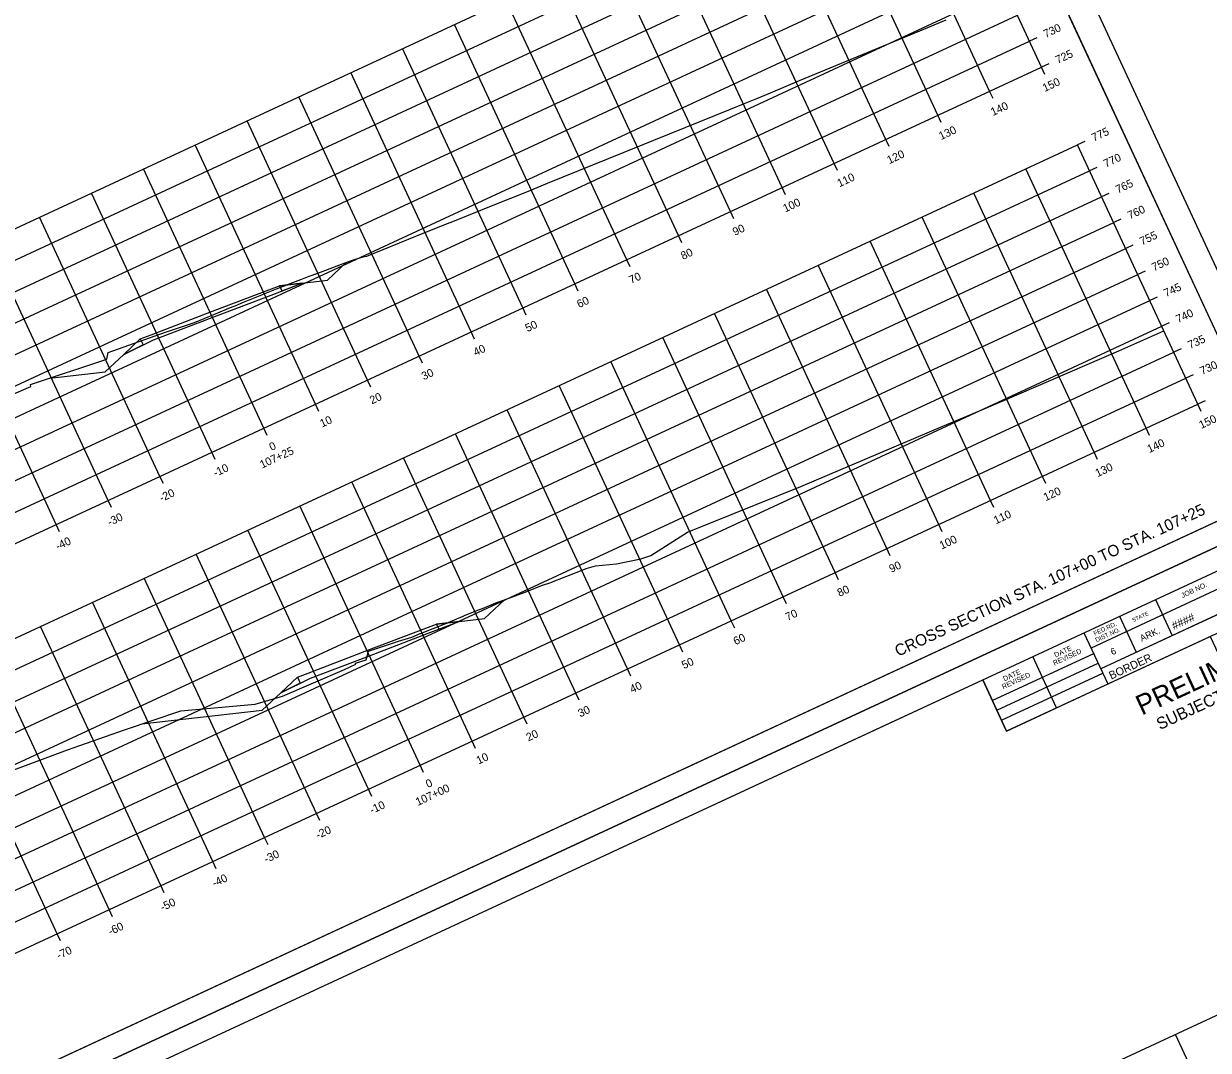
# Model space of a CAD drawing. Extents: x 1354696 to 1366163, y 660729 to 670380.
# Drawn here: x 1355130.4 to 1355337.6, y 664529.6 to 664709.1 of the extents above; entities that cross this region are included whole.
import ezdxf

# ---------------------------------------------------------------- set-up
doc = ezdxf.new("R2010")
doc.units = 0
for name, color, linetype in [('Default', 7, 'Continuous'), ('R_Alt Surface', 7, 'Continuous'), ('R_Axis', 7, 'Continuous'), ('R_Axis Annot', 7, 'Continuous'), ('R_Border', 7, 'Continuous'), ('R_Border Prem', 7, 'Continuous'), ('R_Draft', 7, 'Continuous'), ('R_Exist Surface', 7, 'Continuous'), ('R_Fin Surface', 7, 'Continuous'), ('R_Grid', 7, 'Continuous'), ('R_No Plot', 7, 'Continuous')]:
    doc.layers.add(name, color=color, linetype=linetype)

msp = doc.modelspace()

# ---------------------------------------------------------------- linework, layer by layer
at = {"layer": 'Default'}
for points in [[(1355175.1, 664663.32), (1355175.53, 664662.41), (1355179.08, 664663.77)], [(1355150.76, 664654.02), (1355151.25, 664652.95), (1355147.87, 664651.29)], [(1355202.58, 664604.14), (1355203, 664603.23), (1355206.56, 664604.59)], [(1355178.23, 664594.84), (1355178.73, 664593.77), (1355175.34, 664592.12)]]:
    msp.add_lwpolyline(points, close=True, dxfattribs=at)
at = {"layer": 'R_Alt Surface'}
for points in [[(1355147.87, 664651.29), (1355153.05, 664653.83), (1355163.35, 664657.76), (1355173.65, 664661.69), (1355179.08, 664663.77)], [(1355175.34, 664592.12), (1355180.52, 664594.65), (1355190.83, 664598.58), (1355201.13, 664602.52), (1355206.56, 664604.59)]]:
    msp.add_lwpolyline(points, dxfattribs=at)
at = {"layer": 'R_Axis'}
for p, q in [((1355308.4, 664701.56), (1355287.34, 664746.91)), ((1355307.56, 664706.68), (1355306.29, 664706.09)), ((1355036.29, 664575.23), (1355308.4, 664701.56)), ((1355309.67, 664702.15), (1355308.4, 664701.56)), ((1355308.99, 664700.29), (1355308.4, 664701.56)), ((1355299.92, 664696.08), (1355299.33, 664697.35)), ((1355290.85, 664691.86), (1355290.26, 664693.13)), ((1355281.78, 664687.65), (1355281.19, 664688.92)), ((1355315.98, 664688.54), (1355314.71, 664687.95)), ((1355335.77, 664642.6), (1355314.71, 664687.95)), ((1355272.71, 664683.44), (1355272.12, 664684.71)), ((1355318.09, 664684.01), (1355316.82, 664683.42)), ((1355263.64, 664679.23), (1355263.05, 664680.5)), ((1355320.19, 664679.47), (1355318.92, 664678.88)), ((1355254.57, 664675.02), (1355253.98, 664676.29)), ((1355322.3, 664674.94), (1355321.03, 664674.35)), ((1355245.49, 664670.81), (1355244.91, 664672.08)), ((1355324.4, 664670.4), (1355323.13, 664669.81)), ((1355236.42, 664666.6), (1355235.84, 664667.87)), ((1355326.51, 664665.87), (1355325.24, 664665.28)), ((1355227.35, 664662.39), (1355226.77, 664663.66)), ((1355328.62, 664661.33), (1355327.35, 664660.74)), ((1355218.28, 664658.18), (1355217.69, 664659.45)), ((1355330.72, 664656.8), (1355329.45, 664656.21)), ((1355209.21, 664653.97), (1355208.62, 664655.24)), ((1355332.83, 664652.26), (1355331.56, 664651.67)), ((1355200.14, 664649.75), (1355199.55, 664651.02)), ((1355334.93, 664647.73), (1355333.66, 664647.14)), ((1355191.07, 664645.54), (1355190.48, 664646.81)), ((1355063.66, 664516.27), (1355335.77, 664642.6)), ((1355182, 664641.33), (1355181.41, 664642.6)), ((1355337.04, 664643.19), (1355335.77, 664642.6)), ((1355336.36, 664641.33), (1355335.77, 664642.6)), ((1355172.93, 664637.12), (1355172.34, 664638.39)), ((1355327.29, 664637.12), (1355326.7, 664638.39)), ((1355163.86, 664632.91), (1355163.27, 664634.18)), ((1355318.22, 664632.91), (1355317.63, 664634.18)), ((1355154.79, 664628.7), (1355154.2, 664629.97)), ((1355309.15, 664628.7), (1355308.56, 664629.97)), ((1355145.72, 664624.49), (1355145.13, 664625.76)), ((1355300.08, 664624.49), (1355299.49, 664625.76)), ((1355136.65, 664620.28), (1355136.06, 664621.55)), ((1355291.01, 664620.28), (1355290.42, 664621.55)), ((1355281.94, 664616.06), (1355281.35, 664617.33)), ((1355272.87, 664611.85), (1355272.28, 664613.12)), ((1355263.8, 664607.64), (1355263.21, 664608.91)), ((1355254.73, 664603.43), (1355254.14, 664604.7)), ((1355245.66, 664599.22), (1355245.07, 664600.49)), ((1355236.59, 664595.01), (1355236, 664596.28)), ((1355227.52, 664590.8), (1355226.93, 664592.07)), ((1355218.45, 664586.59), (1355217.86, 664587.86)), ((1355209.38, 664582.38), (1355208.79, 664583.65)), ((1355200.31, 664578.17), (1355199.72, 664579.44)), ((1355191.24, 664573.95), (1355190.65, 664575.22)), ((1355182.17, 664569.74), (1355181.58, 664571.01)), ((1355173.1, 664565.53), (1355172.51, 664566.8)), ((1355164.02, 664561.32), (1355163.44, 664562.59)), ((1355154.95, 664557.11), (1355154.37, 664558.38)), ((1355145.88, 664552.9), (1355145.3, 664554.17)), ((1355136.81, 664548.69), (1355136.22, 664549.96))]:
    msp.add_line(p, q, dxfattribs=at)
at = {"layer": 'R_Border'}
for p, q in [((1355351.61, 664627.9), (1355265.09, 664814.26)), ((1355351.61, 664627.9), (1355064.83, 664494.76)), ((1355068.15, 664487.62), (1355354.93, 664620.76)), ((1355356.16, 664618.09), (1355317.07, 664599.94)), ((1355357.85, 664614.46), (1355318.76, 664596.32)), ((1355321.44, 664597.56), (1355357.85, 664614.46)), ((1355359.09, 664611.8), (1355302.27, 664585.42)), ((1355328.33, 664608.41), (1355331.26, 664602.12)), ((1355322.04, 664605.49), (1355324.96, 664599.2)), ((1355315.83, 664602.61), (1355319.99, 664593.65)), ((1355299.8, 664590.74), (1355317.53, 664598.96)), ((1355311.05, 664589.5), (1355306.89, 664598.46)), ((1355300.59, 664589.05), (1355318.31, 664597.28)), ((1355302.27, 664585.42), (1355298.11, 664594.38)), ((1355301.4, 664587.29), (1355319.13, 664595.52)), ((1355206.59, 664551.61), (1355206.59, 664551.61)), ((1355206.59, 664551.61), (1355206.59, 664551.61))]:
    msp.add_line(p, q, dxfattribs=at)
at = {"layer": 'R_Exist Surface'}
for points in [[(1355128.23, 664644.23), (1355131.62, 664645.7), (1355131.57, 664646.02), (1355144.91, 664650.46), (1355145.15, 664651.62), (1355155.18, 664655.19), (1355160.24, 664656.88), (1355163.6, 664658.26), (1355165.86, 664659.21), (1355166.85, 664659.61), (1355167.35, 664659.81), (1355168.82, 664660.41), (1355171.71, 664661.62), (1355172.84, 664662.06), (1355174.56, 664662.76), (1355175.81, 664663.25), (1355177.42, 664663.87), (1355178.81, 664664.4), (1355180.3, 664664.96), (1355181.82, 664665.52), (1355183.19, 664666.02), (1355185.96, 664667.06), (1355187.89, 664667.78), (1355189.34, 664668.24), (1355189.96, 664668.44), (1355190.37, 664668.51), (1355198.94, 664671.99), (1355204.03, 664674), (1355205.41, 664674.55), (1355212.78, 664677.52), (1355218.4, 664679.71), (1355222.01, 664681.26), (1355254, 664694.2), (1355256.3, 664695.14), (1355258.62, 664696.09), (1355260.99, 664697.06), (1355266.09, 664699.19), (1355287.1, 664707.92), (1355291.75, 664709.85)], [(1355128.16, 664578.44), (1355138.03, 664582.1), (1355147.98, 664585.64), (1355157.83, 664588.93), (1355170.83, 664590.12), (1355175.62, 664591.49), (1355186.49, 664596.2), (1355188.44, 664597.1), (1355188.38, 664597.28), (1355190.27, 664597.9), (1355190.7, 664599.37), (1355195.93, 664601.11), (1355198.25, 664601.84), (1355199.74, 664602.45), (1355199.75, 664602.45), (1355199.75, 664602.45), (1355204.18, 664604.2), (1355204.38, 664604.28), (1355204.61, 664604.38), (1355207.22, 664605.52), (1355207.58, 664605.67), (1355210.09, 664606.68), (1355210.6, 664606.87), (1355212.96, 664607.82), (1355213.63, 664608.07), (1355215.86, 664608.91), (1355217.91, 664609.66), (1355219.23, 664610.19), (1355220.38, 664610.62), (1355221.13, 664610.93), (1355222.41, 664611.35), (1355228.34, 664613.7), (1355228.77, 664613.86), (1355230.38, 664614.33), (1355234.03, 664614.68), (1355238.34, 664615.52), (1355240.06, 664616.12), (1355246.46, 664620.21), (1355266.28, 664628.22), (1355291.15, 664638.73), (1355296.06, 664640.76), (1355301.5, 664643.11), (1355321.94, 664651.9), (1355329.83, 664655.4)]]:
    msp.add_lwpolyline(points, dxfattribs=at)
at = {"layer": 'R_Fin Surface'}
for points in [[(1355134.91, 664647.13), (1355144.62, 664648.23), (1355147.87, 664651.29), (1355150.76, 664654.02), (1355152.63, 664654.73), (1355162.93, 664658.67), (1355173.23, 664662.6), (1355175.1, 664663.32), (1355179.08, 664663.77), (1355183.48, 664664.27), (1355186.76, 664667.36)], [(1355151.05, 664586.67), (1355172.1, 664589.05), (1355175.34, 664592.12), (1355178.23, 664594.84), (1355180.1, 664595.56), (1355190.4, 664599.49), (1355200.71, 664603.43), (1355202.58, 664604.14), (1355206.56, 664604.59), (1355210.96, 664605.09), (1355214.44, 664608.37)]]:
    msp.add_lwpolyline(points, dxfattribs=at)
at = {"layer": 'R_Grid'}
for p, q in [((1355015.24, 664620.58), (1355287.34, 664746.91)), ((1355308.4, 664701.56), (1355287.34, 664746.91)), ((1355017.34, 664616.04), (1355289.45, 664742.37)), ((1355299.33, 664697.35), (1355278.27, 664742.7)), ((1355019.45, 664611.51), (1355291.55, 664737.84)), ((1355290.26, 664693.13), (1355269.2, 664738.49)), ((1355021.55, 664606.97), (1355293.66, 664733.3)), ((1355281.19, 664688.92), (1355260.13, 664734.27)), ((1355023.66, 664602.44), (1355295.76, 664728.77)), ((1355272.12, 664684.71), (1355251.06, 664730.06)), ((1355025.76, 664597.9), (1355297.87, 664724.23)), ((1355263.05, 664680.5), (1355241.99, 664725.85)), ((1355253.98, 664676.29), (1355232.92, 664721.64)), ((1355027.87, 664593.37), (1355299.97, 664719.7)), ((1355244.91, 664672.08), (1355223.85, 664717.43)), ((1355029.98, 664588.83), (1355302.08, 664715.16)), ((1355235.84, 664667.87), (1355214.78, 664713.22)), ((1355032.08, 664584.3), (1355304.19, 664710.63)), ((1355226.77, 664663.66), (1355205.71, 664709.01)), ((1355034.19, 664579.76), (1355306.29, 664706.09)), ((1355217.69, 664659.45), (1355196.64, 664704.8)), ((1355036.29, 664575.23), (1355308.4, 664701.56)), ((1355208.62, 664655.24), (1355187.57, 664700.59)), ((1355199.55, 664651.02), (1355178.5, 664696.37)), ((1355190.48, 664646.81), (1355169.43, 664692.16)), ((1355042.61, 664561.62), (1355314.71, 664687.95)), ((1355181.41, 664642.6), (1355160.36, 664687.95)), ((1355335.77, 664642.6), (1355314.71, 664687.95)), ((1355044.71, 664557.09), (1355316.82, 664683.42)), ((1355172.34, 664638.39), (1355151.29, 664683.74)), ((1355326.7, 664638.39), (1355305.64, 664683.74)), ((1355046.82, 664552.55), (1355318.92, 664678.88)), ((1355163.27, 664634.18), (1355142.22, 664679.53)), ((1355317.63, 664634.18), (1355296.57, 664679.53)), ((1355154.2, 664629.97), (1355133.15, 664675.32)), ((1355308.56, 664629.97), (1355287.5, 664675.32)), ((1355048.93, 664548.02), (1355321.03, 664674.35)), ((1355145.13, 664625.76), (1355124.08, 664671.11)), ((1355299.49, 664625.76), (1355278.43, 664671.11)), ((1355051.03, 664543.48), (1355323.13, 664669.81)), ((1355136.06, 664621.55), (1355115.01, 664666.9)), ((1355290.42, 664621.55), (1355269.36, 664666.9)), ((1355053.14, 664538.95), (1355325.24, 664665.28)), ((1355281.35, 664617.33), (1355260.29, 664662.69)), ((1355055.24, 664534.41), (1355327.35, 664660.74)), ((1355272.28, 664613.12), (1355251.22, 664658.47)), ((1355057.35, 664529.88), (1355329.45, 664656.21)), ((1355263.21, 664608.91), (1355242.15, 664654.26)), ((1355059.45, 664525.34), (1355331.56, 664651.67)), ((1355254.14, 664604.7), (1355233.08, 664650.05)), ((1355061.56, 664520.81), (1355333.66, 664647.14)), ((1355245.07, 664600.49), (1355224.01, 664645.84)), ((1355063.66, 664516.27), (1355335.77, 664642.6)), ((1355236, 664596.28), (1355214.94, 664641.63)), ((1355226.93, 664592.07), (1355205.87, 664637.42)), ((1355217.86, 664587.86), (1355196.8, 664633.21)), ((1355208.79, 664583.65), (1355187.73, 664629)), ((1355199.72, 664579.44), (1355178.66, 664624.79)), ((1355190.65, 664575.22), (1355169.59, 664620.57)), ((1355181.58, 664571.01), (1355160.52, 664616.36)), ((1355172.51, 664566.8), (1355151.45, 664612.15)), ((1355163.44, 664562.59), (1355142.38, 664607.94)), ((1355154.37, 664558.38), (1355133.31, 664603.73)), ((1355145.3, 664554.17), (1355124.24, 664599.52)), ((1355136.22, 664549.96), (1355115.17, 664595.31)), ((1355105.07, 664427.08), (1355377.18, 664553.41)), ((1355352.88, 664487), (1355331.83, 664532.35))]:
    msp.add_line(p, q, dxfattribs=at)
at = {"layer": 'R_No Plot'}
for q in [(1355357.6, 664626.3), (1355357.6, 664626.29)]:
    msp.add_line((1355055.26, 664485.93), q, dxfattribs=at)
for points in [[(1354965.42, 664679.42), (1355267.76, 664819.79), (1355357.6, 664626.29), (1355055.25, 664485.92)], [(1355190.48, 664779.62), (1355208.27, 664787.88), (1355212.43, 664778.92), (1355227.05, 664785.71), (1355248.09, 664795.47), (1355260.06, 664769.99), (1355281.11, 664779.76), (1355351.61, 664627.9), (1355064.83, 664494.76), (1354978.31, 664681.12)], [(1355055.25, 664485.92), (1355357.6, 664626.29), (1355447.43, 664432.79), (1355145.09, 664292.42)], [(1355280.32, 664586.12), (1355298.11, 664594.38), (1355302.27, 664585.42), (1355316.89, 664592.21), (1355337.93, 664601.97), (1355349.89, 664576.49), (1355370.94, 664586.26), (1355441.45, 664434.4), (1355154.67, 664301.26), (1355068.15, 664487.62)]]:
    msp.add_lwpolyline(points, close=True, dxfattribs=at)

# ---------------------------------------------------------------- texts
at = {"layer": 'R_Axis Annot'}
for s, p in [('730', (1355309.13, 664706.64)), ('725', (1355311.23, 664702.1)), ('150', (1355308.97, 664697.19)), ('140', (1355299.9, 664692.98)), ('130', (1355290.83, 664688.77)), ('775', (1355317.55, 664688.5)), ('120', (1355281.76, 664684.56)), ('770', (1355319.65, 664683.96)), ('110', (1355273.05, 664680.52)), ('765', (1355321.76, 664679.43)), ('100', (1355263.57, 664676.11)), ('760', (1355323.86, 664674.89)), ('90', (1355254.76, 664672.02)), ('755', (1355325.97, 664670.36)), ('80', (1355245.69, 664667.81)), ('750', (1355328.07, 664665.82)), ('70', (1355236.62, 664663.6)), ('745', (1355330.18, 664661.29)), ('60', (1355227.52, 664659.38)), ('740', (1355332.29, 664656.75)), ('50', (1355218.48, 664655.18)), ('735', (1355334.39, 664652.21)), ('40', (1355209.41, 664650.97)), ('730', (1355336.5, 664647.68)), ('30', (1355200.34, 664646.76)), ('20', (1355191.27, 664642.55)), ('10', (1355182.56, 664638.5)), ('150', (1355336.34, 664638.24)), ('107+25', (1355172.05, 664631.31)), ('0', (1355173.7, 664634.39)), ('140', (1355327.27, 664634.03)), ('-10', (1355163.9, 664629.84)), ('130', (1355318.2, 664629.81)), ('-20', (1355154.47, 664625.46)), ('120', (1355309.13, 664625.6)), ('-30', (1355145.4, 664621.25)), ('110', (1355300.42, 664621.56)), ('-40', (1355136.33, 664617.04)), ('100', (1355290.94, 664617.16)), ('90', (1355282.13, 664613.07)), ('80', (1355273.06, 664608.86)), ('70', (1355263.99, 664604.65)), ('60', (1355254.89, 664600.42)), ('50', (1355245.85, 664596.22)), ('40', (1355236.78, 664592.01)), ('30', (1355227.71, 664587.8)), ('20', (1355218.64, 664583.59)), ('10', (1355209.93, 664579.55)), ('107+00', (1355199.31, 664572.3)), ('0', (1355201.07, 664575.43)), ('-10', (1355191.27, 664570.88)), ('-20', (1355181.84, 664566.51)), ('-30', (1355172.77, 664562.29)), ('-40', (1355163.7, 664558.08)), ('-50', (1355154.63, 664553.87)), ('-60', (1355145.53, 664549.65)), ('-70', (1355136.49, 664545.45))]:
    msp.add_text(s, height=1.4, rotation=24.9042, dxfattribs=at).set_placement(p)
at = {"layer": 'R_Border'}
for s, height, p in [('JOB NO.', 0.879, (1355333.07, 664608.67)), ('STATE', 0.684, (1355324.46, 664604.45)), ('FED.RD.', 0.782, (1355317.72, 664602.07)), ('####', 1.4, (1355331.58, 664603.08)), ('DIST.NO.', 0.782, (1355318.03, 664600.92)), ('ARK.', 1.172, (1355325.94, 664601.04)), ('DATE', 0.879, (1355310.87, 664598.25)), ('6', 1.17, (1355320.8, 664598.65)), ('REVISED', 0.879, (1355310.66, 664596.85)), ('BORDER', 1.4, (1355320.6, 664594.4)), ('DATE', 0.879, (1355301.92, 664594.1)), ('REVISED', 0.879, (1355301.71, 664592.7))]:
    msp.add_text(s, height=height, rotation=24.9042, dxfattribs=at).set_placement(p)
at = {"layer": 'R_Border Prem'}
for s, height, p in [('PRELIMINARY', 3.5, (1355325.94, 664588.1)), ('SUBJECT TO REVISION', 2.0751, (1355329.11, 664585.57)), ('DWB', 0.01, (1355325.83, 664590.09))]:
    msp.add_text(s, height=height, rotation=24.9042, dxfattribs=at).set_placement(p)
at = {"layer": 'R_Draft'}
msp.add_text('CROSS SECTION STA. 107+00 TO STA. 107+25', height=2, rotation=24.9042, dxfattribs=at).set_placement((1355283.31, 664598.4))

doc.saveas('drawing.dxf')
